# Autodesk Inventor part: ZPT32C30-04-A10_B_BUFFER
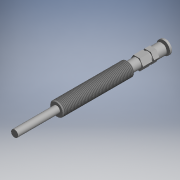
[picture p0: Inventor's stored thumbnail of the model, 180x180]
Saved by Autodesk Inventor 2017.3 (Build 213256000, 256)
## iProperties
Part Number: ZPT32C30-04-A10_B_BUFFER
Material: Generic
Catalog Web Link: www.cadenas.de
Description: ZPT_20_32B_BUFFER-Vacuum Pad/Vertical Vacuum Entry With Buffer
Vendor: SMC
Document SubType Name: Modeling
Designer: partserver
Manufacturer: SMC
Mass: 5.31182 g
Surface Area: 38.1936 cm^2
Volume: 5.31182 cm^3
Density: 1 g/cm^3
Appearance: PSOLRGB-192-192-192
Category: PARTsolutions
Company: SMC
Title: ZPT32C30-04-A10_B_BUFFER
Author: Cadenas PARTsolutions
Comments: Vacuum Pad/Vertical Vacuum Entry With Buffer
PSOL_IDENT_0: {$CADENAS_DATA\23d-libs\smc_jp\vacuum_equipment\vacuum_pad\zp\zpt_b\zpt_20_32_b\parts\zpt_20_32_buff
PSOL_IDENT_1: er_b.prj},217 {VTYP=3D},{NB=ZPT32C30-04-A10_B_BUFFER},{LINA=ZPT32C30-04-A10_B_BUFFER},{NN=ZPT_20_32B
PSOL_IDENT_2: _BUFFER},{DATE=03.02.2021 04:15:19},{GEOMDATE=19.04.2012 02:41:00},{VERSION=},{LINEID=130},{WBVAR=ST
PSOL_IDENT_3: ROKE,PORT},{WBNUMERIC=STROKE}  {NB=ZPT32C30-04-A10_B_BUFFER},{LINA=ZPT32C30-04-A10_B_BUFFER},{KT=DUM
PSOL_IDENT_4: MY},{DIAMETER=32},{PAD=(C) Flat with ribs},{PADX=C},{STROKE=30},{PORT=04},{MOUNT=(A10) M10x1 (Male t
PSOL_IDENT_5: hread)},{ORDER=ZPT32C30-04-A10},{TIFX=U2},{A=32.000},{B=35.000},{C=14.500},{D=23.500},{Y=2.300},{E=5
PSOL_IDENT_6: 5},{F=133},{G=51},{FB5=0},{F04=133},{FN6U6=121}
NB: ZPT32C30-04-A10_B_BUFFER
NN: ZPT_20_32B_BUFFER
NT: Vacuum Pad/Vertical Vacuum Entry With Buffer
NBSYN: $ORDER._B_BUFFER
LINA: ZPT32C30-04-A10_B_BUFFER
CATALOG: SMC (JP
DIAMETER: 32
PAD: (C) Flat with ribs
STROKE: 30
PORT: (04) dia 4 tube (One-touch fitting)
MOUNT: (A10) M10x1 (Male thread)
A: 32
B: 35
C: 14.5
D: 23.5
Y: 2.3
E: 55
F: 133
G: 51
SUPPLIER: SMC
ARTICLENO: ZPT32C30-04-A10_B_BUFFER
BOMINFO: ZPT32C30-04-A10_B_BUFFER
CREATOR: CADENAS GmbH
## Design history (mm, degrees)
sketch "Sketch_1"
  geometry: L1 (0, 25)-(0, 106); L2 (0, 106)-(4.386, 106); L3 (4.386, 106)-(5, 105.387); L4 (5, 105.387)-(5, 55.614); L5 (5, 55.614)-(4.386, 55); L6 (4.386, 55)-(2.5, 55); L7 (2.5, 55)-(2.5, 25); L8 (2.5, 25)-(0, 25); L9 (0, 25)-(0, 106)
  constraints: 18 end point
revolve "Revolution1" sketch "Sketch_1" stored, may be unused: angle "d0" = 360 deg
thread "Thread1" dims "d1" = 49.773, "d2" = 0
sketch "Sketch_2"
  geometry: L1 (0, 106)-(0, 112.35); L2 (0, 112.35)-(3.5, 112.35); L3 (3.5, 112.35)-(3.5, 106); L4 (3.5, 106)-(0, 106); L5 (0, 106)-(0, 112.35)
  constraints: 10 end point
revolve "Revolution2" sketch "Sketch_2" stored, may be unused: angle "d3" = 360 deg
sketch "Sketch_3"
  geometry: L1 (-4.619, 0)-(-2.309, -4); L2 (-2.309, -4)-(2.309, -4); L3 (2.309, -4)-(4.619, 0); L4 (4.619, 0)-(2.309, 4); L5 (2.309, 4)-(-2.309, 4); L6 (-2.309, 4)-(-4.619, 0)
  constraints: 12 end point
extrude "Extrusion1" join sketch "Sketch_3" distance "d4" = 6.65; taper "d5" = 0 deg
sketch "Sketch_8"
  geometry: L1 (0, 119)-(0, 120.3); L2 (0, 120.3)-(3.45, 120.3); L3 (3.45, 120.3)-(3.45, 119); L4 (3.45, 119)-(0, 119); L5 (0, 119)-(0, 120.3)
  constraints: 10 end point
revolve "Revolution3" sketch "Sketch_8" stored, may be unused: angle "d6" = 360 deg
sketch "Sketch_10"
  geometry: L1 (-4.561, 0)-(-2.281, -3.95); L2 (-2.281, -3.95)-(2.281, -3.95); L3 (2.281, -3.95)-(4.561, 0); L4 (4.561, 0)-(2.281, 3.95); L5 (2.281, 3.95)-(-2.281, 3.95); L6 (-2.281, 3.95)-(-4.561, 0)
  constraints: 12 end point
extrude "Extrusion2" join sketch "Sketch_10" distance "d7" = 3.8; taper "d8" = 0 deg
sketch "Sketch_11"
  geometry: L1 (0, 124.1)-(0, 133); L2 (0, 133)-(4.75, 133); L3 (4.75, 133)-(4.75, 131.5); L4 (4.75, 131.5)-(2.05, 131.5); L5 (2.05, 131.5)-(2.05, 130); L6 (2.05, 130)-(3.95, 130); L7 (3.95, 130)-(3.95, 124.1); L8 (3.95, 124.1)-(0, 124.1); L9 (0, 124.1)-(0, 133)
  constraints: 18 end point
revolve "Revolution4" sketch "Sketch_11" stored, may be unused: angle "d9" = 360 deg
sketch "Sketch_12"
  geometry: L1 (0, 45)-(0, 133); L2 (0, 133)-(2, 133); L3 (2, 133)-(2, 119); L4 (2, 119)-(1.621, 118.621); L5 (1.621, 118.621)-(1.621, 115); L6 (1.621, 115)-(1.25, 114.786); L7 (1.25, 114.786)-(1.25, 45); L8 (1.25, 45)-(0, 45); L9 (0, 45)-(0, 133)
  constraints: 18 end point
revolve "Revolution5" sketch "Sketch_12" stored, may be unused: angle "d10" = 360 deg
thread "Thread2" dims "d11" = 3.621, "d12" = 0
node "NUT_XY"
node "NUT_YZ"
node "NUT_ZX"
node "NUT_X"
node "NUT_Y"
node "NUT_Z"
node "NUT_Center"
node "NUT2_XY"
node "NUT2_YZ"
node "NUT2_ZX"
node "NUT2_X"
node "NUT2_Y"
node "NUT2_Z"
node "NUT2_Center"
node "adapter_XY"
node "adapter_YZ"
node "adapter_ZX"
node "adapter_X"
node "adapter_Y"
node "adapter_Z"
node "adapter_Center"
body "Solid1"
other parameters: "d13" = 0
